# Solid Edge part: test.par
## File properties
Author: CADCIM
Template: Normal.par
Last saved by: CADCIM
Revision: 3
Application: Solid Edge
Density: 0 kg/mm^3
Accuracy: 0.99
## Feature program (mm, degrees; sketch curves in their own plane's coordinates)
sketch for "unnamed Protrusion 1" #1 plane through (0, 0, 0) normal (0, 0, 1) x-axis (1, 0, 0)
  line (-47.52, 0) -> (-47.52, 46.944)
  line (-47.52, 46.944) -> (47.52, 46.944)
  line (47.52, 46.944) -> (47.52, 0)
  line (47.52, 0) -> (-47.52, 0)
sketch for "unnamed Protrusion 1" #2 plane through (0, 0, 0) normal (0, 0, 1) x-axis (1, 0, 0)
  circle centre (-33.4173, 33.1293) radius 7.1111
sketch for "unnamed Protrusion 1" #3 plane through (0, 0, 0) normal (0, 0, 1) x-axis (1, 0, 0)
  circle centre (0, 13.2015) radius 7.2161
sketch for "unnamed Protrusion 1" #4 plane through (0, 0, 0) normal (0, 0, 1) x-axis (1, 0, 0)
  circle centre (36.4831, 33.1293) radius 6.1622
extrude "unnamed Protrusion 1" add finite 6.35 along +normal
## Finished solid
Body 1: solid body, 9 faces, 18 edges, 8 vertices.
  Faces by surface: plane 6, cylinder 3
  Edges by curve: line 12, circle 6
Bounding box of the edges (mm): 95.040 x 46.944 x 6.350, from (-47.52, 0, 0) to (47.52, 46.944, 6.35).
Cylindrical faces by radius (mm): R6.1622 x1, R7.1111 x1, R7.2161 x1
Planar faces by outward normal: +x 1, +y 1, +z 1, -x 1, -y 1, -z 1
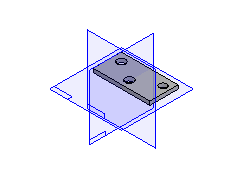
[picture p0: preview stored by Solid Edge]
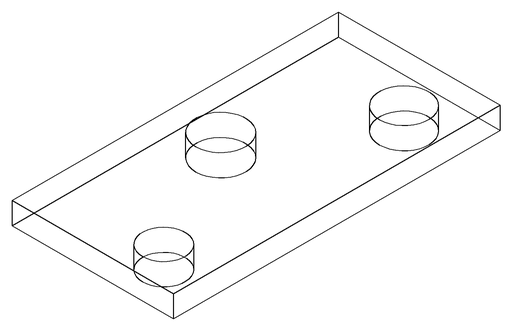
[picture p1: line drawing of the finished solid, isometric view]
